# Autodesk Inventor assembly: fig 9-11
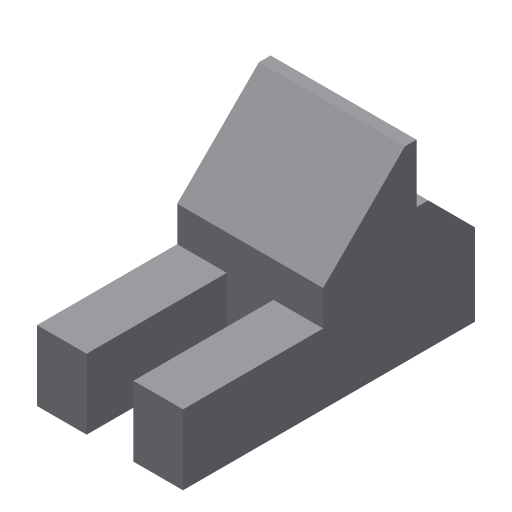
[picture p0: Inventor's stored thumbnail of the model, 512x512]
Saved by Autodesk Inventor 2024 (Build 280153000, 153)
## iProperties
Shininess: 64.0
Length Units: 11269
Angle Units: 11279
Time Units: 11290
Mass Units: 11283
Length Display Precision: 3
Angle Display Precision: 2
Created: 2002-01
Part Number: fig 9-11
Document SubType Name: Assembly
Designer: ***
Density: 0.0
Volumn: 0.0
Area: 0.0
PropertySet Name: Model Information
Control State: 0
Master: False
Checked Out: False
Author: ***
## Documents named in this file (3)
- D:\PROJECTS\Project 2023\RESOURCES INVENTOR 2024\RESOURCES INVENTOR 2024\Inventor_2023_Part\Inventor_2024_Part\c09_Inv_2024_prt\fig 9-11.iam
- D:\PROJECTS\Project 2023\RESOURCES INVENTOR 2024\RESOURCES INVENTOR 2024\Inventor_2023_Part\Inventor_2024_Part\c09_Inv_2024_prt\Part3.ipt
- D:\PROJECTS\Project 2023\RESOURCES INVENTOR 2024\RESOURCES INVENTOR 2024\Inventor_2023_Part\Inventor_2024_Part\c09_Inv_2024_prt\Part4.ipt
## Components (2 placed, 2 different names)
1. Part3:1 — Mate:1
2. Part4:1 — Mate:1
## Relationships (1: Mate 1)
- Mate:1: Part3:1 ↔ Part4:1
